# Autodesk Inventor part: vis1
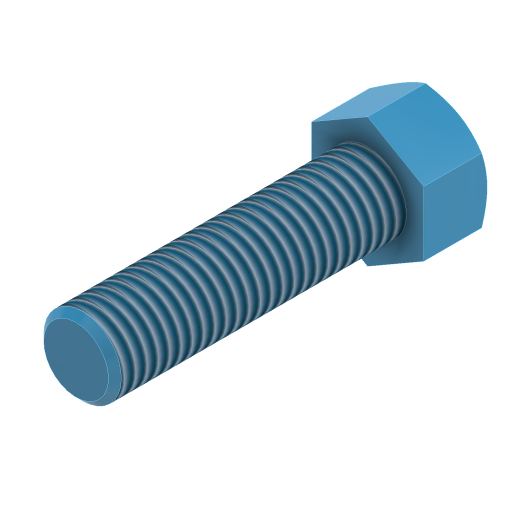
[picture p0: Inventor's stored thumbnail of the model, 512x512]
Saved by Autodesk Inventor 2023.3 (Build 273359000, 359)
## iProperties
Created: 2024-11
Part Number: vis1
Material: Générique
Description: STEP AP203
Document SubType Name: Modeling
Designer: Thier
Density: 1 g/cm^3
Appearance: Bleu ciel foncé
Sending System: SolidWorks 2017
Preprocessor: SwSTEP 2.0
Title: vis1.STEP
Revision Number: ANY
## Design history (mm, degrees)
feature "Chanfrein1"
feature "Filetage1" dims "d0" = 44, "d1" = 0
node "Solide1"
